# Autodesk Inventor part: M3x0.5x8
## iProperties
Company: 한국ATC센터
IsCustomPart: 1
Created: 2009-02
Part Number: M3x0.5x8
Material: 고무
Description: 오일-실
Document SubType Name: Modeling
Standard: KS B 2804
Designer: KYOUNG IL JANG
Standards Organization: KS
Language: ko-KR
Size Designation: S - 12 22 7
Categories: <MemberInstance><Categories><Category DisplayName="샤프트 부품" InternalName="7f7aeb1f-a693-4053-b835-cee3144e0d98" Mnemonic="SHFT"><Category DisplayName="실링" Intern
Density: 0.93 g/cm^3
Mass: 1.0258 g
Surface Area: 17.5559 cm^2
Volume: 1.10301 cm^3
Vendor: CBT Solutions
Author: KYOUNG IL JANG
